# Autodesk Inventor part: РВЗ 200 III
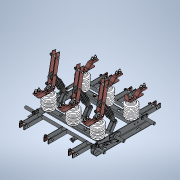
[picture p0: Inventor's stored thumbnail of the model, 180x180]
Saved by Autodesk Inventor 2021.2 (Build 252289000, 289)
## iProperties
Created: 1900-01
Part Number: РВЗ 200 III
Material: Типовые
Description: STEP AP242
Document SubType Name: Modeling
Designer: pc
Density: 1 g/cm^3
Appearance: По умолчанию
Company: UNSPECIFIED
Title: ÐÂÇ 200 III
Author: UNSPECIFIED
Revision Number: ANYUNSPECIFIED
Sending System: C3D Toolkit
Preprocessor: C3D Converter
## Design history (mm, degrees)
feature "БазТело1"
feature "БазТело2"
feature "БазТело3"
feature "БазТело4"
feature "БазТело5"
feature "БазТело6"
feature "БазТело7"
feature "БазТело8"
feature "БазТело9"
feature "БазТело10"
feature "БазТело11"
feature "БазТело12"
feature "Составной1"
node "Твердое тело1"
node "Твердое тело2"
node "Твердое тело3"
node "Твердое тело4"
node "Твердое тело5"
node "Твердое тело6"
node "Твердое тело7"
node "Твердое тело8"
node "Твердое тело9"
node "Твердое тело10"
node "Твердое тело11"
node "Твердое тело12"
body "SRF1"
